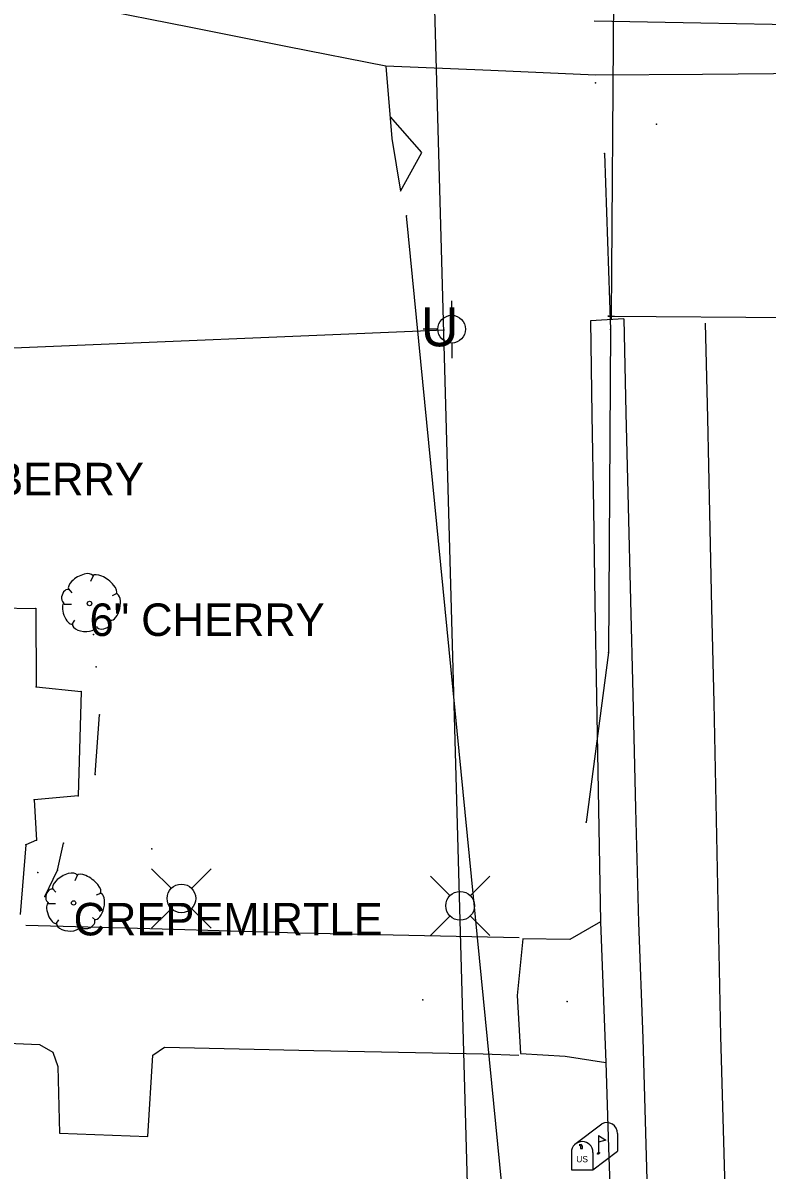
# Model space of a CAD drawing. Extents: x 1930288 to 1941089, y 588389 to 611475.
# Drawn here: x 1930769.5 to 1930884, y 598005.7 to 598182.1 of the extents above; entities that cross this region are included whole.
import ezdxf

# ---------------------------------------------------------------- set-up
doc = ezdxf.new("R2010")
doc.units = 0
for name, color, linetype in [('Default', 7, 'Continuous'), ('S_BRIDGE', 7, 'Continuous'), ('S_BUILDING', 7, 'Continuous'), ('S_DITCHLINE', 7, 'Continuous'), ('S_DRIVEWAY', 7, 'Continuous'), ('S_EDGE_PAVEMENT', 7, 'Continuous'), ('S_GUARDRAIL', 7, 'Continuous'), ('S_MAILBOX', 7, 'Continuous'), ('S_MSC_PT_SYM', 7, 'Continuous'), ('S_PAVEMENT_CROWN', 7, 'Continuous'), ('S_RDW_PT_SYM', 7, 'Continuous'), ('S_SHOULDER', 7, 'Continuous'), ('S_STORM_SEWER', 7, 'Continuous'), ('S_STR_PT_SYM', 7, 'Continuous'), ('S_STREAM', 7, 'Continuous'), ('S_TREE', 7, 'Continuous'), ('S_TREE_ANNOT', 7, 'Continuous'), ('S_UNDERGROUND_CABLE', 7, 'Continuous'), ('S_UTILITY_POLE', 7, 'Continuous'), ('S_UTL_PT_SYM', 7, 'Continuous'), ('S_WATER_UTILITIES', 7, 'Continuous')]:
    doc.layers.add(name, color=color, linetype=linetype)

msp = doc.modelspace()

# ---------------------------------------------------------------- linework, layer by layer
at = {"layer": 'S_BRIDGE'}
for p, q in [((1930860.72, 598227), (1930860.05, 598137.01)), ((1930860.05, 598137.01), (1930887.7, 598136.81))]:
    msp.add_line(p, q, dxfattribs=at)
at = {"layer": 'S_BUILDING'}
for p, q in [((1930721.4, 598092.94), (1930771.5, 598092.05)), ((1930771.5, 598092.05), (1930771.54, 598079.99)), ((1930771.54, 598079.99), (1930778.49, 598079.29)), ((1930778.49, 598079.29), (1930778.04, 598063.23)), ((1930778.04, 598063.23), (1930771.25, 598062.61)), ((1930771.25, 598062.61), (1930771.59, 598056.41)), ((1930769.97, 598055.71), (1930769.07, 598044.99)), ((1930771.59, 598056.41), (1930769.97, 598055.71))]:
    msp.add_line(p, q, dxfattribs=at)
at = {"layer": 'S_DITCHLINE'}
for points in [[(1930905.69, 598176.9), (1930890.32, 598181.8), (1930873.87, 598182.1), (1930857.41, 598182.4)], [(1930825.38, 598175.47), (1930826.3, 598164.35), (1930827.64, 598156.24), (1930830.9, 598162.19), (1930826.1, 598167.67)]]:
    msp.add_lwpolyline(points, dxfattribs=at)
at = {"layer": 'S_DRIVEWAY'}
for points in [[(1930845.9, 598041.38), (1930828.93, 598041.75), (1930811.96, 598042.12), (1930790.97, 598042.71), (1930769.98, 598043.29)], [(1930858.39, 598043.88), (1930853.67, 598041.13), (1930846.43, 598041.24), (1930845.58, 598032.53), (1930846.11, 598023.6), (1930852.99, 598023.2), (1930859.23, 598022.21)], [(1930752.46, 598025.79), (1930772.06, 598025.01), (1930774.1, 598023.8), (1930774.87, 598021.62), (1930775.13, 598011.33), (1930788.72, 598010.83), (1930789.53, 598023.35), (1930791.28, 598024.6), (1930814.28, 598024.07), (1930827.31, 598023.8), (1930840.35, 598023.53), (1930845.84, 598023.33)]]:
    msp.add_lwpolyline(points, dxfattribs=at)
at = {"layer": 'S_EDGE_PAVEMENT'}
msp.add_lwpolyline([(1930861.97, 598136.6), (1930862.32, 598122.16), (1930862.67, 598107.72), (1930863.02, 598093.28), (1930863.37, 598078.84), (1930863.8, 598061.3), (1930864.24, 598043.75), (1930864.93, 598025.92), (1930865.59, 598002.39), (1930866.24, 597978.87), (1930866.59, 597966.32), (1930866.95, 597953.76), (1930867.3, 597941.21), (1930867.66, 597928.66), (1930868.33, 597905.09), (1930869.01, 597881.53), (1930869.59, 597857.83), (1930870.18, 597834.13), (1930870.73, 597810.89), (1930871.29, 597787.65)], dxfattribs=at)
at = {"layer": 'S_GUARDRAIL'}
for p, q in [((1930859, 598162.05), (1930859.95, 598134.96)), ((1930859.95, 598134.96), (1930859.64, 598085.31)), ((1930859.64, 598085.31), (1930856.18, 598059.19))]:
    msp.add_line(p, q, dxfattribs=at)
at = {"layer": 'S_MAILBOX'}
for p, q in [((1930854.48, 598009.68), (1930858.61, 598012.79)), ((1930858.09, 598010.97), (1930858.09, 598008.25)), ((1930861.04, 598011.31), (1930861.04, 598008.6)), ((1930853.92, 598008.4), (1930853.92, 598005.69)), ((1930857.25, 598005.69), (1930861.04, 598008.6)), ((1930857.25, 598008.4), (1930857.25, 598005.69)), ((1930853.92, 598005.69), (1930857.25, 598005.69))]:
    msp.add_line(p, q, dxfattribs=at)
for points in [[(1930858.09, 598010.97), (1930859.2, 598010.3), (1930858.09, 598009.96)], [(1930855.11, 598009.52), (1930855.33, 598009.38), (1930855.33, 598008.99), (1930855.64, 598008.99), (1930855.64, 598009.35), (1930855.44, 598009.6), (1930855.11, 598009.55)]]:
    msp.add_lwpolyline(points, dxfattribs=at)
for centre, end in [((1930859.38, 598011.31), 117.5718), ((1930855.59, 598008.4), 180)]:
    msp.add_arc(centre, 1.66, 0, end, dxfattribs=at)
msp.add_ellipse((1930858.09, 598008.25), major_axis=(0.145, 0.132), ratio=0.564646, dxfattribs=at)
at = {"layer": 'S_MSC_PT_SYM'}
for points in [[(1930857.64, 598172.93), (1930857.64, 598172.98), (1930857.64, 598172.93), (1930857.59, 598172.93), (1930857.64, 598172.93), (1930857.64, 598172.88), (1930857.64, 598172.93), (1930857.69, 598172.93)], [(1930867.02, 598166.54), (1930867.02, 598166.59), (1930867.02, 598166.54), (1930866.97, 598166.54), (1930867.02, 598166.54), (1930867.02, 598166.49), (1930867.02, 598166.54), (1930867.07, 598166.54)], [(1930828.55, 598152.44), (1930828.55, 598152.49), (1930828.55, 598152.44), (1930828.5, 598152.44), (1930828.55, 598152.44), (1930828.55, 598152.39), (1930828.55, 598152.44), (1930828.6, 598152.44)], [(1930780.38, 598088.04), (1930780.38, 598088.09), (1930780.38, 598088.04), (1930780.33, 598088.04), (1930780.38, 598088.04), (1930780.38, 598087.99), (1930780.38, 598088.04), (1930780.43, 598088.04)], [(1930780.77, 598083.1), (1930780.77, 598083.15), (1930780.77, 598083.1), (1930780.72, 598083.1), (1930780.77, 598083.1), (1930780.77, 598083.05), (1930780.77, 598083.1), (1930780.82, 598083.1)], [(1930781.32, 598075.69), (1930781.32, 598075.74), (1930781.32, 598075.69), (1930781.27, 598075.69), (1930781.32, 598075.69), (1930781.32, 598075.64), (1930781.32, 598075.69), (1930781.37, 598075.69)], [(1930780.64, 598066.51), (1930780.64, 598066.56), (1930780.64, 598066.51), (1930780.59, 598066.51), (1930780.64, 598066.51), (1930780.64, 598066.46), (1930780.64, 598066.51), (1930780.69, 598066.51)], [(1930775.74, 598055.95), (1930775.74, 598056), (1930775.74, 598055.95), (1930775.69, 598055.95), (1930775.74, 598055.95), (1930775.74, 598055.9), (1930775.74, 598055.95), (1930775.79, 598055.95)], [(1930789.34, 598055.09), (1930789.34, 598055.14), (1930789.34, 598055.09), (1930789.29, 598055.09), (1930789.34, 598055.09), (1930789.34, 598055.04), (1930789.34, 598055.09), (1930789.39, 598055.09)], [(1930771.79, 598051.43), (1930771.79, 598051.48), (1930771.79, 598051.43), (1930771.74, 598051.43), (1930771.79, 598051.43), (1930771.79, 598051.38), (1930771.79, 598051.43), (1930771.84, 598051.43)], [(1930774.86, 598051.81), (1930774.86, 598051.86), (1930774.86, 598051.81), (1930774.81, 598051.81), (1930774.86, 598051.81), (1930774.86, 598051.76), (1930774.86, 598051.81), (1930774.91, 598051.81)], [(1930772.91, 598047.73), (1930772.91, 598047.78), (1930772.91, 598047.73), (1930772.86, 598047.73), (1930772.91, 598047.73), (1930772.91, 598047.68), (1930772.91, 598047.73), (1930772.96, 598047.73)], [(1930831.05, 598031.86), (1930831.05, 598031.91), (1930831.05, 598031.86), (1930831, 598031.86), (1930831.05, 598031.86), (1930831.05, 598031.81), (1930831.05, 598031.86), (1930831.1, 598031.86)], [(1930853.26, 598031.59), (1930853.26, 598031.64), (1930853.26, 598031.59), (1930853.21, 598031.59), (1930853.26, 598031.59), (1930853.26, 598031.54), (1930853.26, 598031.59), (1930853.31, 598031.59)]]:
    msp.add_lwpolyline(points, dxfattribs=at)
at = {"layer": 'S_PAVEMENT_CROWN'}
msp.add_lwpolyline([(1930874.52, 598135.93), (1930874.85, 598121.34), (1930875.18, 598106.75), (1930875.51, 598092.15), (1930875.84, 598077.56), (1930876.1, 598064.74), (1930876.35, 598051.91), (1930876.61, 598039.09), (1930876.86, 598026.27), (1930877.56, 598002.85), (1930878.25, 597979.44), (1930878.66, 597966.75), (1930879.07, 597954.07), (1930879.48, 597941.38), (1930879.89, 597928.7), (1930880.57, 597904.97), (1930881.24, 597881.25), (1930881.88, 597857.6), (1930882.52, 597833.95), (1930883.18, 597810.9), (1930883.85, 597787.85)], dxfattribs=at)
at = {"layer": 'S_RDW_PT_SYM'}
for points in [[(1930859, 598162.05), (1930859, 598162.1), (1930859, 598162.05), (1930858.95, 598162.05), (1930859, 598162.05), (1930859, 598162), (1930859, 598162.05), (1930859.05, 598162.05)], [(1930859.95, 598134.96), (1930859.95, 598135.01), (1930859.95, 598134.96), (1930859.9, 598134.96), (1930859.95, 598134.96), (1930859.95, 598134.91), (1930859.95, 598134.96), (1930860, 598134.96)], [(1930859.64, 598085.31), (1930859.64, 598085.36), (1930859.64, 598085.31), (1930859.59, 598085.31), (1930859.64, 598085.31), (1930859.64, 598085.26), (1930859.64, 598085.31), (1930859.69, 598085.31)], [(1930856.18, 598059.19), (1930856.18, 598059.24), (1930856.18, 598059.19), (1930856.13, 598059.19), (1930856.18, 598059.19), (1930856.18, 598059.14), (1930856.18, 598059.19), (1930856.23, 598059.19)]]:
    msp.add_lwpolyline(points, dxfattribs=at)
at = {"layer": 'S_SHOULDER'}
msp.add_lwpolyline([(1930861.97, 598136.6), (1930856.85, 598136.29), (1930857.08, 598121.84), (1930857.31, 598107.38), (1930857.54, 598092.92), (1930857.77, 598078.47), (1930858.08, 598061.18), (1930858.39, 598043.88), (1930859.23, 598022.21), (1930859.65, 598009.16), (1930860.08, 597996.1), (1930860.58, 597972.84), (1930861.09, 597949.57), (1930861.39, 597937.48), (1930861.77, 597924.84), (1930862.15, 597912.21), (1930862.82, 597887.9), (1930863.5, 597863.59), (1930864.03, 597839.11), (1930864.57, 597814.62), (1930865.11, 597791.12)], dxfattribs=at)
at = {"layer": 'S_STORM_SEWER'}
msp.add_line((1930843.2, 598003.4), (1930828.55, 598152.44), dxfattribs=at)
at = {"layer": 'S_STR_PT_SYM'}
for points in [[(1930860.05, 598137.01), (1930860.05, 598137.51), (1930860.05, 598137.01), (1930859.55, 598137.01), (1930860.05, 598137.01), (1930860.05, 598136.51), (1930860.05, 598137.01), (1930860.55, 598137.01)], [(1930771.5, 598092.05), (1930771.5, 598092.1), (1930771.5, 598092.05), (1930771.45, 598092.05), (1930771.5, 598092.05), (1930771.5, 598092), (1930771.5, 598092.05), (1930771.55, 598092.05)], [(1930771.54, 598079.99), (1930771.54, 598080.04), (1930771.54, 598079.99), (1930771.49, 598079.99), (1930771.54, 598079.99), (1930771.54, 598079.94), (1930771.54, 598079.99), (1930771.59, 598079.99)], [(1930778.49, 598079.29), (1930778.49, 598079.34), (1930778.49, 598079.29), (1930778.44, 598079.29), (1930778.49, 598079.29), (1930778.49, 598079.24), (1930778.49, 598079.29), (1930778.54, 598079.29)], [(1930771.25, 598062.61), (1930771.25, 598062.66), (1930771.25, 598062.61), (1930771.2, 598062.61), (1930771.25, 598062.61), (1930771.25, 598062.56), (1930771.25, 598062.61), (1930771.3, 598062.61)], [(1930778.04, 598063.23), (1930778.04, 598063.28), (1930778.04, 598063.23), (1930777.99, 598063.23), (1930778.04, 598063.23), (1930778.04, 598063.18), (1930778.04, 598063.23), (1930778.09, 598063.23)], [(1930771.59, 598056.41), (1930771.59, 598056.46), (1930771.59, 598056.41), (1930771.54, 598056.41), (1930771.59, 598056.41), (1930771.59, 598056.36), (1930771.59, 598056.41), (1930771.64, 598056.41)], [(1930769.97, 598055.71), (1930769.97, 598055.76), (1930769.97, 598055.71), (1930769.92, 598055.71), (1930769.97, 598055.71), (1930769.97, 598055.66), (1930769.97, 598055.71), (1930770.02, 598055.71)]]:
    msp.add_lwpolyline(points, dxfattribs=at)
at = {"layer": 'S_STREAM'}
msp.add_lwpolyline([(1930903.84, 598172.42), (1930890.52, 598174.33), (1930874.09, 598174.21), (1930857.65, 598174.09), (1930841.52, 598174.78), (1930825.38, 598175.47), (1930810.24, 598178.46), (1930795.11, 598181.46), (1930779.97, 598184.46)], dxfattribs=at)
at = {"layer": 'S_TREE'}
for p, q in [((1930780.33, 598097.08), (1930779.94, 598096.23)), ((1930776.53, 598095.06), (1930777.03, 598094.48)), ((1930783.89, 598094.29), (1930783.23, 598094.02)), ((1930775.87, 598092.74), (1930776.99, 598092.74)), ((1930777.03, 598089.56), (1930777.5, 598090.26)), ((1930780.71, 598089.29), (1930780.64, 598090.06)), ((1930783.12, 598090.18), (1930782.65, 598090.61)), ((1930780.64, 598066.51), (1930781.32, 598075.69)), ((1930774.86, 598051.81), (1930775.74, 598055.95)), ((1930772.91, 598047.73), (1930774.86, 598051.81)), ((1930777.88, 598051.01), (1930777.49, 598050.16)), ((1930774.08, 598049), (1930774.59, 598048.42)), ((1930781.45, 598048.22), (1930780.79, 598047.95)), ((1930773.42, 598046.67), (1930774.55, 598046.67)), ((1930774.59, 598043.5), (1930775.05, 598044.19)), ((1930780.67, 598044.12), (1930780.21, 598044.54)), ((1930778.27, 598043.23), (1930778.19, 598044))]:
    msp.add_line(p, q, dxfattribs=at)
for centre in [(1930779.77, 598092.83), (1930777.32, 598046.77)]:
    msp.add_circle(centre, 0.341, dxfattribs=at)
for centre, major_axis, ratio, start_param, end_param in [((1930778.43, 598096.03), (1.86, 1.08), 0.471018, 0, 3.141593), ((1930782.09, 598095.71), (-1.81, 1.36), 0.405113, 3.141593, 6.283186), ((1930776.2, 598093.92), (0.31, 1.03), 0.646762, 0, 3.141593), ((1930783.44, 598092.3), (0.46, 2.04), 0.482994, 3.141593, 6.283185), ((1930776.5, 598091.27), (-0.61, 1.6), 0.420543, 6.283185, 9.424777), ((1930781.92, 598089.78), (1.09, 0.46), 0.711534, 3.141592, 6.283185), ((1930778.96, 598089.49), (-1.83, 0.19), 0.529943, 0, 3.141593), ((1930775.99, 598049.97), (1.86, 1.08), 0.471018, 0, 3.141593), ((1930779.64, 598049.65), (-1.81, 1.36), 0.405113, 3.141593, 6.283186), ((1930773.75, 598047.86), (0.31, 1.03), 0.646762, 0, 3.141593), ((1930781, 598046.24), (0.46, 2.04), 0.482994, 3.141593, 6.283185), ((1930774.06, 598045.21), (-0.61, 1.6), 0.420543, 6.283185, 9.424777), ((1930779.47, 598043.72), (1.09, 0.46), 0.711534, 3.141592, 6.283185), ((1930776.52, 598043.43), (-1.83, 0.19), 0.529943, 0, 3.141593)]:
    msp.add_ellipse(centre, major_axis=major_axis, ratio=ratio, start_param=start_param, end_param=end_param, dxfattribs=at)
at = {"layer": 'S_UNDERGROUND_CABLE'}
msp.add_line((1930623.81, 598126.06), (1930834.39, 598134.93), dxfattribs=at)
at = {"layer": 'S_UTILITY_POLE'}
for p, q in [((1930835.51, 598137.13), (1930835.51, 598139.38)), ((1930833.42, 598135), (1930831.09, 598135)), ((1930835.59, 598130.58), (1930835.59, 598132.91)), ((1930792.32, 598049.04), (1930789.33, 598052.02)), ((1930795.49, 598049.04), (1930798.48, 598052.02)), ((1930835.21, 598047.91), (1930832.22, 598050.9)), ((1930838.38, 598047.91), (1930841.37, 598050.9)), ((1930792.32, 598045.86), (1930789.33, 598042.88)), ((1930795.49, 598045.86), (1930798.48, 598042.88)), ((1930835.21, 598044.74), (1930832.22, 598041.75)), ((1930838.38, 598044.74), (1930841.37, 598041.75))]:
    msp.add_line(p, q, dxfattribs=at)
for centre, radius in [((1930835.51, 598135.02), 2.13), ((1930793.91, 598047.46), 2.21), ((1930836.8, 598046.33), 2.21)]:
    msp.add_circle(centre, radius, dxfattribs=at)
at = {"layer": 'S_UTL_PT_SYM'}
msp.add_lwpolyline([(1930828.55, 598152.44), (1930828.55, 598152.49), (1930828.55, 598152.44), (1930828.5, 598152.44), (1930828.55, 598152.44), (1930828.55, 598152.39), (1930828.55, 598152.44), (1930828.6, 598152.44)], dxfattribs=at)
at = {"layer": 'S_WATER_UTILITIES'}
msp.add_line((1930831.37, 598238.21), (1930837.98, 598000.7), dxfattribs=at)

# ---------------------------------------------------------------- texts
at = {"layer": 'Default'}
msp.add_text('U', height=6, rotation=360, dxfattribs=at).set_placement((1930830.76, 598132.38))
at = {"layer": 'S_MAILBOX'}
msp.add_text('US', height=0.96, rotation=360, dxfattribs=at).set_placement((1930854.69, 598006.88))
at = {"layer": 'S_TREE_ANNOT'}
for s, p in [('32" MULBERRY', (1930739.31, 598109.46)), ('6" CHERRY', (1930779.77, 598087.83)), ('CREPEMIRTLE', (1930777.32, 598041.77))]:
    msp.add_text(s, height=5, dxfattribs=at).set_placement(p)

doc.saveas('drawing.dxf')
